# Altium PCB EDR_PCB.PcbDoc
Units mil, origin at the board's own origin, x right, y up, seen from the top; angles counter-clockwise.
Board outline 1445 x 1620 mil, 2 copper layers (Top Layer, Bottom Layer); 11 components, 9 nets, 54 pads, 0 vias.
Unrouted connection lines stored in the file: 1.
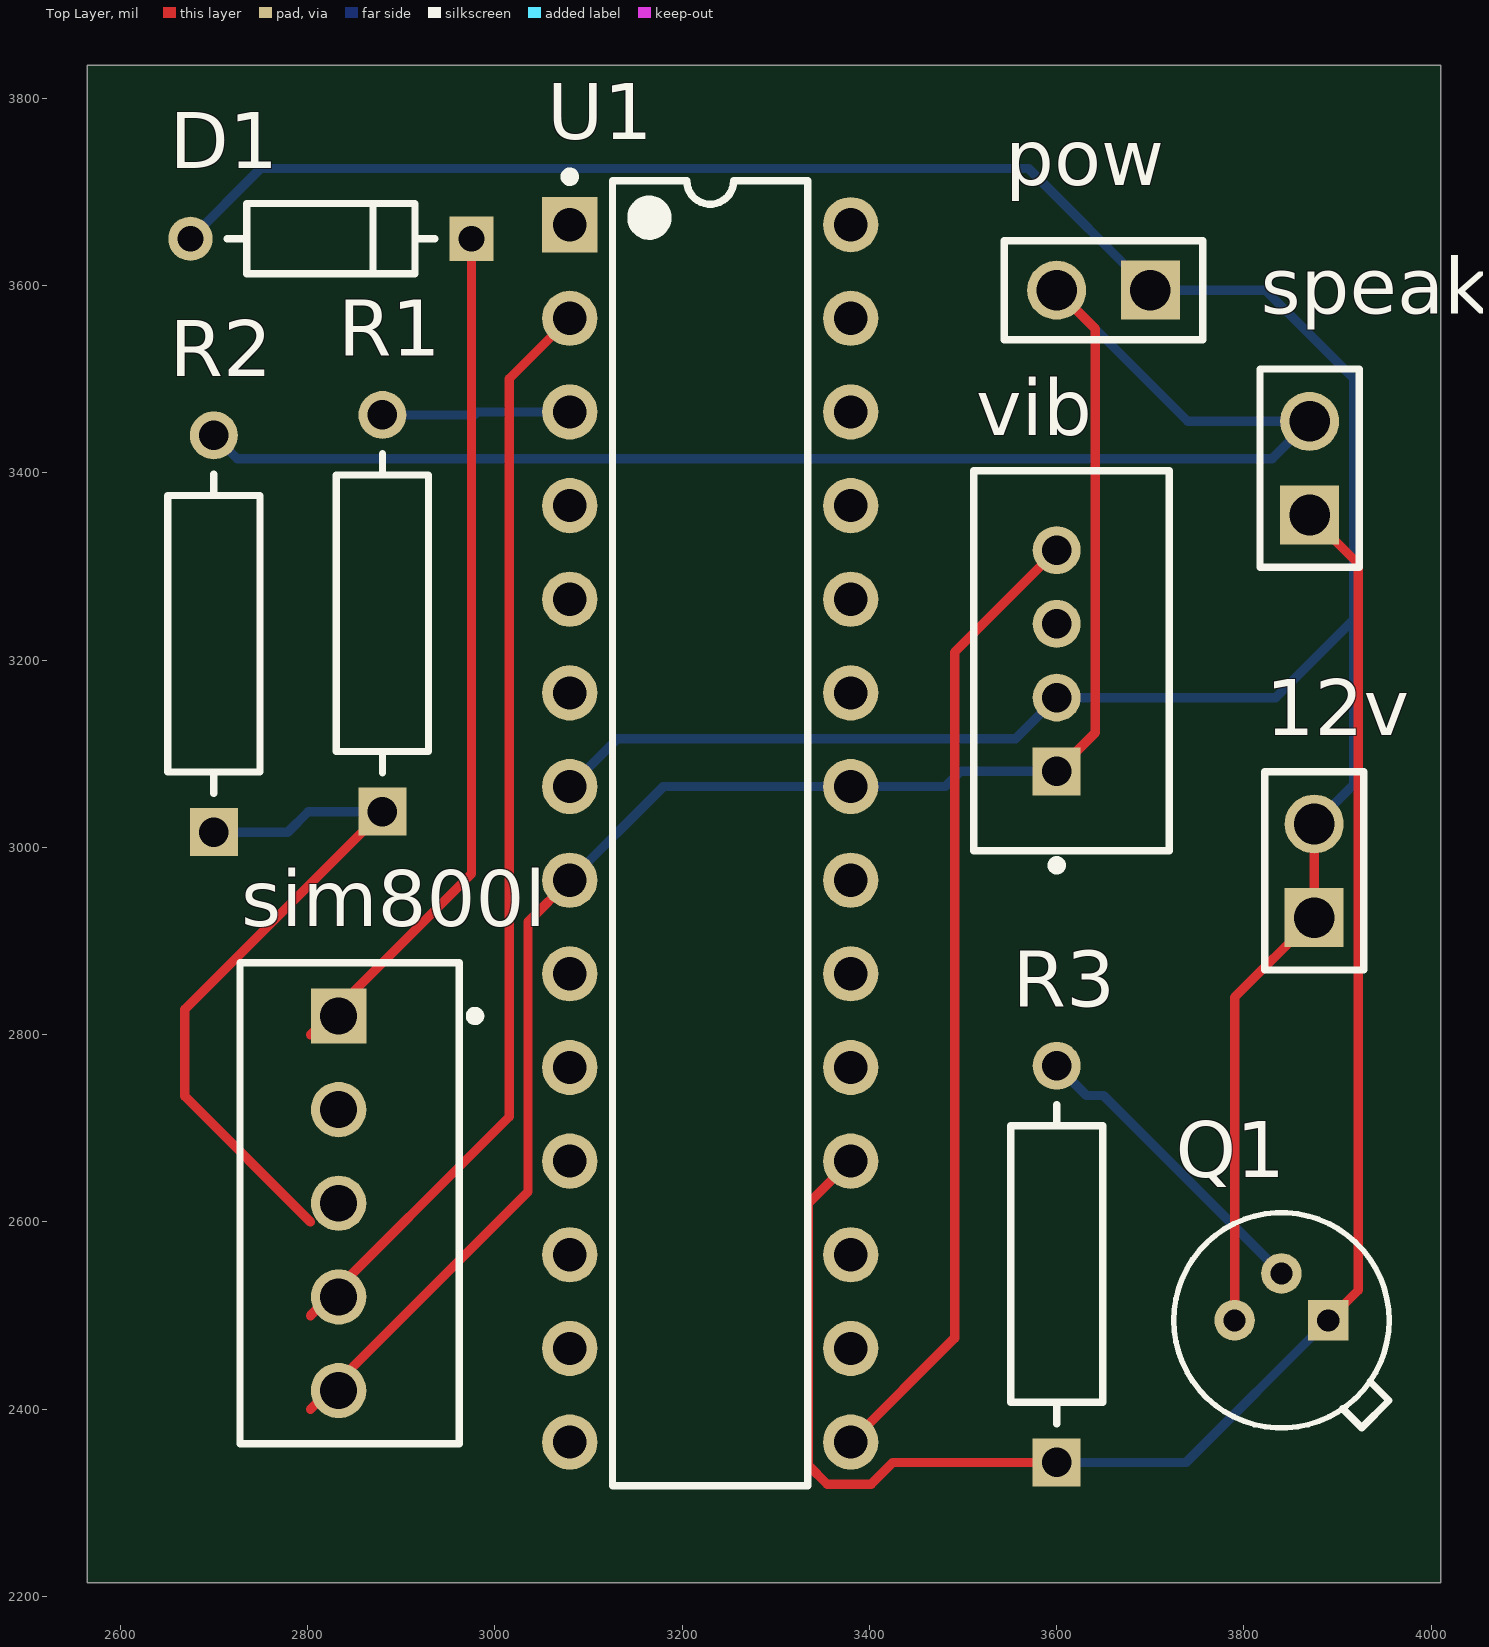
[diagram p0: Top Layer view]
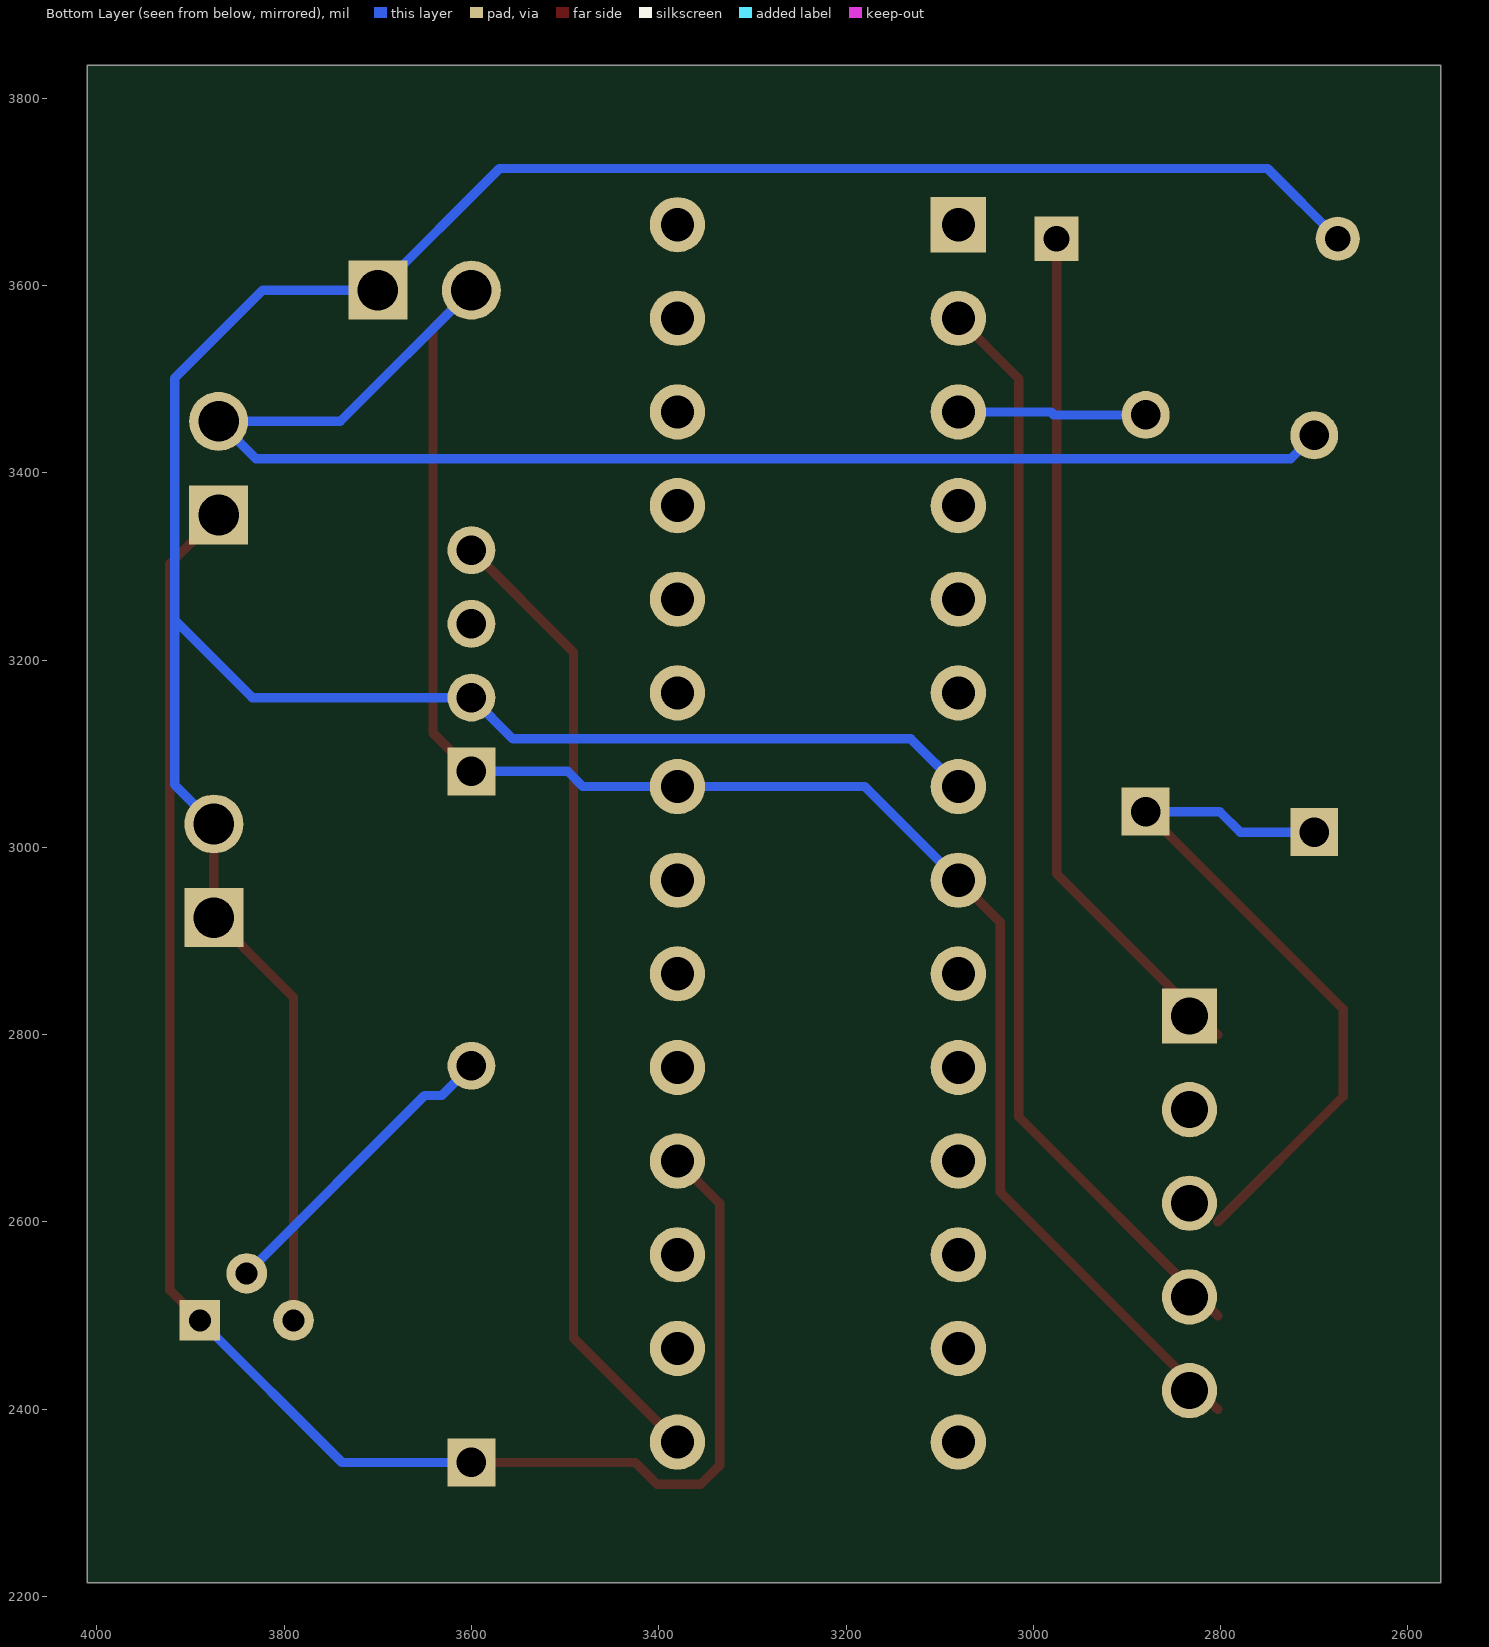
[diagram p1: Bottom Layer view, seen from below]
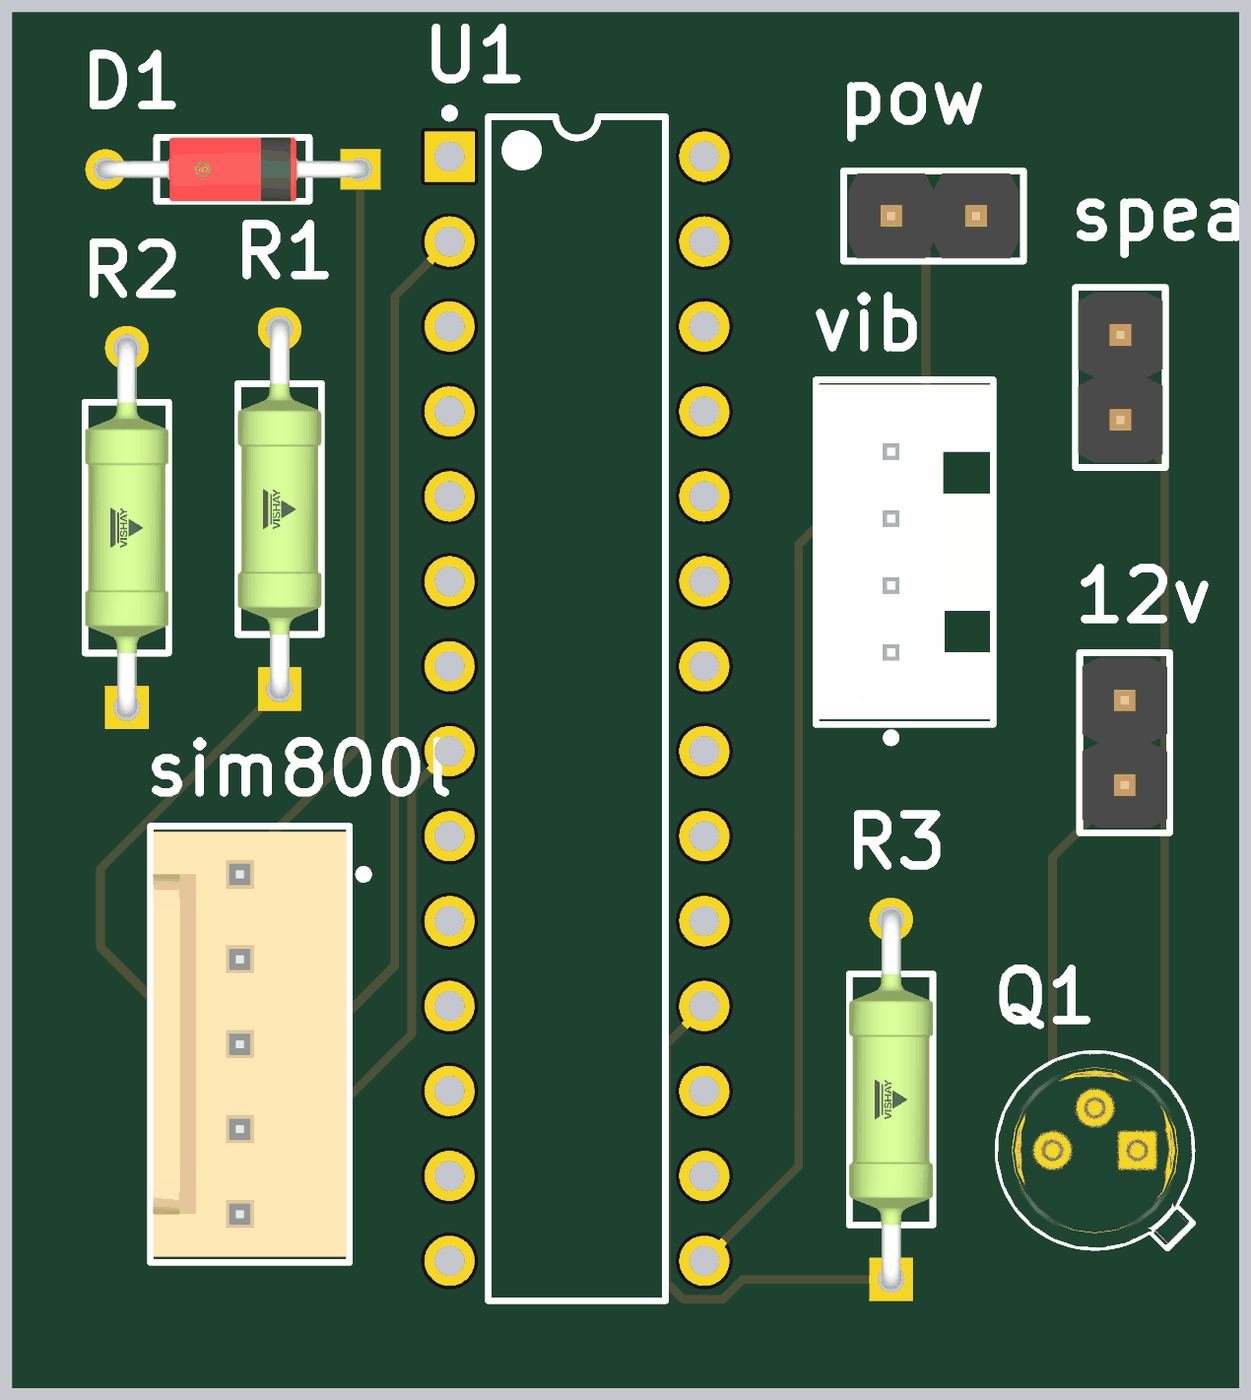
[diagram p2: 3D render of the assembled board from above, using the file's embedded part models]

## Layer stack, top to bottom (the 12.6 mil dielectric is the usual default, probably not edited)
Top Solder: solder mask 0.4, Solder Resist, Dk 3.5
Top Layer: signal copper 1.4
Dielectric 1: dielectric 12.6, FR-4, Dk 4.8
Bottom Layer: signal copper 1.4
Bottom Solder: solder mask 0.4, Solder Resist, Dk 3.5

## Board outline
2565,2215 4010,2215 4010,3835 2565,3835

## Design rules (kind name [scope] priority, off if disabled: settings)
Clearance [All] p1: gap=10 ignorepadtopadclearanceinfootprint=FALSE except(0: Arc-Hole Track-Hole SMDPad-Hole THPad-Hole Via-Hole Fill-Hole Poly-Hole Region-Hole Text-Hole)
PolygonConnect [All] p1: connectstyle=Relief reliefconductorwidth=10 reliefentries=4 polygonreliefangle="90 Angle" airgapwidth=10
RoutingVias [All] p1: holewidth=28 width=50 viastyle="Through Hole" minholewidth=28 minwidth=50 maxholewidth=28 maxwidth=50
SolderMaskExpansion [All] p1: expansion=4 istentingtop=FALSE
Width [All] p1: maxlimit=10 minlimit=10 preferedwidth=10
30 further rules are at their usual default settings.

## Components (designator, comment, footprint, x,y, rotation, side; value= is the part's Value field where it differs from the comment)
12v "" 61300211121 3875,2975 r90 top
D1 "1N4148TR" FP-017AG-MFG 2825,3650 r180 top value=4pF
pow "" 61300211121 3650,3595 r180 top
Q1 "2N2222A" FP-2N2222A-MFG 3840,2495 r0 top
R1 "" FP-SFR25-MFG 2880,3250 r90 top
R2 "" FP-SFR25-MFG 2700,3228.19 r90 top
R3 "" FP-SFR25-MFG 3600,2555 r90 top
sim800l "" 61900511121 2845,2620 r90 top
speaker "" 61300211121 3870,3405 r90 top
U1 "ATmega328P-PU" 28P3 3230,3015 r0 top
vib "vib sen" FP-110990030-MFG 3615.75,3199.37 r90 top

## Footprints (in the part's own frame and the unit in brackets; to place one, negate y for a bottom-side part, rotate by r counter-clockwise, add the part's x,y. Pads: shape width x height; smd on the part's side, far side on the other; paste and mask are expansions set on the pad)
28P3 [mm] "28-Pin Plastic Dual In-Line Package (PDIP)"
  rect 1.5x1.5 hole 0.9: 1(-3.81,16.51)
  round 1.5 hole 0.9: 2(-3.81,13.97) 3(-3.81,11.43) 4(-3.81,8.89) 5(-3.81,6.35) 6(-3.81,3.81) 7(-3.81,1.27) 8(-3.81,-1.27) 9(-3.81,-3.81) 10(-3.81,-6.35) 11(-3.81,-8.89) 12(-3.81,-11.43) 13(-3.81,-13.97) 14(-3.81,-16.51) 15(3.81,-16.51) 16(3.81,-13.97) 17(3.81,-11.43) 18(3.81,-8.89) 19(3.81,-6.35) 20(3.81,-3.81) 21(3.81,-1.27) 22(3.81,1.27) 23(3.81,3.81) 24(3.81,6.35) 25(3.81,8.89) 26(3.81,11.43) 27(3.81,13.97) 28(3.81,16.51)
  silkscreen extent -3.93,-17.7 2.65,17.93, body extent -3.6,-17.65 3.6,17.65, height 4.58
61300211121 [mm] "Pin Header, pitch 2.54 mm, THT, Vertical, single row, 2p"
  rect 1.6x1.6 hole 1.1: 1(-1.27,0)
  round 1.6 hole 1.1: 2(1.27,0)
  silkscreen extent -2.69,-1.34 2.69,1.34, body extent -2.54,-1.27 2.54,1.27, height 8.57
61900511121 [mm] "2.54mm Male Locking Header, 5p"
  rect 1.5x1.5 hole 1: 1(5.08,0.3)
  round 1.5 hole 1: 2(2.54,0.3) 3(0,0.3) 4(-2.54,0.3) 5(-5.08,0.3)
  silkscreen extent -6.52,-3.52 6.52,2.98, body extent -6.35,-2.9 6.35,2.9, height 11.53
FP-2N2222A-MFG [mm]
  rect 1.1x1.1 hole 0.6 paste-1000 mask+0: 1(1.27,0)
  round 1.1 hole 0.6 paste-1000 mask+0: 2(0,1.27) 3(-1.27,0)
  silkscreen extent -2.92,-2.92 2.92,2.92, body extent -3.02,-3.02 3.02,3.02, height 0.25
FP-017AG-MFG [mm]
  rect 1.2x1.2 hole 0.7 paste-1000 mask+0: 1(-3.813,0)
  round 1.2 hole 0.7 paste-1000 mask+0: 2(3.813,0)
  silkscreen extent -2.81,-0.95 2.81,0.95, body extent -4.51,-1.05 4.51,1.05, height 0.25
FP-110990030-MFG [mm]
  rect 1.3x1.3 hole 0.8 paste-1000 mask+0: 1(-3,0.4)
  round 1.3 hole 0.8 paste-1000 mask+0: 2(-1,0.4) 3(1,0.4) 4(3,0.4)
  silkscreen extent -5.67,-2.65 5.15,2.65, body extent -5.25,-2.75 5.25,2.75, height 0.25
FP-SFR25-MFG [mm]
  rect 1.3x1.3 hole 0.8 paste-1000 mask+0: 1(-5.38,0)
  round 1.3 hole 0.8 paste-1000 mask+0: 2(5.38,0)
  silkscreen extent -4.33,-1.25 4.33,1.25, body extent -6.13,-1.35 6.13,1.35, height 0.25

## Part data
12v pow speaker: library part CMP-1712-00002-4, "THT Vertical Pin Header WR-PHD, Pitch 2.54 mm, Single Row, 2 pins", Contact Resistance=20mOhm, Manufacturer="Wurth Elektronik", Operating Temperature=-40to105degC, Package Reference=61300211121, Rated Current=3A, Withstanding Voltage=500VAC, Working Voltage=250VAC
D1: library part CMP-07163-000030-1, "DIODE GEN PURP 100V 200MA DO35", Capacitance=4pF, Forward Current=200mA, Manufacturer="ON Semiconductor", Max Junction Temp=+175°C, Max Repetitive Reverse Voltage=100V, Max Surge Forward Current=1A, Package=017AG, Peak Reverse Current=5uA, Temperature="-55°C to +175°C", Temperature Range Low=-55°C
Q1: library part CMP-50385-000001-1, "T-NPN SI- AUDIO VHF AMP", Case/Package=TO-18, Collector Emitter Breakdown Voltage=40V, Max Operating Temperature=200°C, Max Power Dissipation=1.2W, Transition Frequency=300MHz
R1: library part CMP-02408-000013-1, "RES 0 OHM JUMPER MF", Case/Package=Conformal, Max Operating Temperature=155°C, Min Operating Temperature=-55°C, Package Quantity=5000, Resistance=10k, Resistor Type="Metal Film"
R2: library part CMP-02408-000013-1, "RES 0 OHM JUMPER MF", Case/Package=Conformal, Max Operating Temperature=155°C, Min Operating Temperature=-55°C, Package Quantity=5000, Resistance=20k, Resistor Type="Metal Film"
R3: library part CMP-02408-000013-1, "RES 0 OHM JUMPER MF", Case/Package=Conformal, Max Operating Temperature=155°C, Min Operating Temperature=-55°C, Package Quantity=5000, Resistance=1.8k, Resistor Type="Metal Film"
sim800l: library part CMP-1502-00587-1, "Male Locking Header WR-WTB, THT, Vertical, pitch 2.54 mm, 1 x 5 position", Contact Resistance=20mOhm, Manufacturer="Wurth Elektronik", Operating Temperature=-40to105degC, Package Reference=61900511121, Working Voltage=250VAC
U1: library part CMP-0095-00013-2, "8-bit AVR Microcontroller, 32KB Flash, 1KB EEPROM, 2KB SRAM, 28-pin PDIP, Industrial Grade (-40°C to 85°C)"
vib: library part CMP-139044-000001-1, "GROVE 2MM 4PIN VERT CONN 10PCS"

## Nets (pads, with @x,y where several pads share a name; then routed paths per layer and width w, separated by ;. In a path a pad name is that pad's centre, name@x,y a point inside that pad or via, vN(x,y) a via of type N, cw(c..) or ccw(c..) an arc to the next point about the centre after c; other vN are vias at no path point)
GND: pow.2 R2.2 sim800l.5 speaker.2 U1.8 U1.22 vib.1 | length 3320.4
  Top Layer w10: 2803.19,2400 3035.47,2632.28 3035.47,2920.47 U1.8 ; vib.1 3641,3122.26 3641,3554 pow.2
  Bottom Layer w10: R2.2 2725,3415 3830,3415 speaker.2 3740,3455 pow.2 ; U1.8 3180,3065 U1.22 3481,3065 3497.26,3081.26 vib.1
NetD1_1: D1.1 sim800l.1 | length 921.2
  Top Layer w10: 2803.19,2800 2975.12,2971.93 D1.1
NetQ1_1: Q1.1 R3.1 speaker.1 U1.18 | length 1874.2
  Top Layer w10: U1.18 3335,2620 3335,2340 3355,2320 3401.81,2320 3425,2343.19 R3.1 ; speaker.1 3922,3303 3922,2527 Q1.1
  Bottom Layer w10: R3.1 3738.19,2343.19 Q1.1
NetQ1_2: Q1.2 R3.2 | length 331.9
  Bottom Layer w10: R3.2 3631.81,2735 3650,2735 Q1.2
NetR1_1: R1.1 R2.1 sim800l.3 | length 770.2
  Top Layer w10: 2803.19,2600 2669,2734.19 2669,2827.19 R1.1
  Bottom Layer w10: R2.1 2779,3016.38 2800.81,3038.19 R1.1
NetR1_2: R1.2 U1.3 | length 201.3
  Bottom Layer w10: R1.2 2978,3461.81 2981.19,3465 U1.3
Netsim800l_4: sim800l.4 U1.2 | length 1179.7
  Top Layer w10: 2803.19,2500 3015.47,2712.28 3015.47,3500.47 U1.2
NetU1_15: U1.15 vib.4 | length 1043.6
  Top Layer w10: U1.15 3491,2476 3491,3208.48 vib.4
VCC: 12v.1 12v.2 D1.2 pow.1 Q1.3 U1.7 vib.2 | length 3335.3
  Top Layer w10: Q1.3 3790,2840 12v.1 12v.2
  Bottom Layer w10: D1.2 2749.88,3725 3570,3725 pow.1 3823,3595 3917,3501 3917,3243 ; U1.7 3131,3116 3556,3116 vib.2 3834,3160 3917,3243 ; 12v.2 3917,3067 3917,3243
pads on no net: sim800l.2 U1.1 U1.4 U1.5 U1.6 U1.9 U1.10 U1.11 U1.12 U1.13 U1.14 U1.16 U1.17 U1.19 U1.20 U1.21 U1.23 U1.24 U1.25 U1.26 U1.27 U1.28 vib.3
